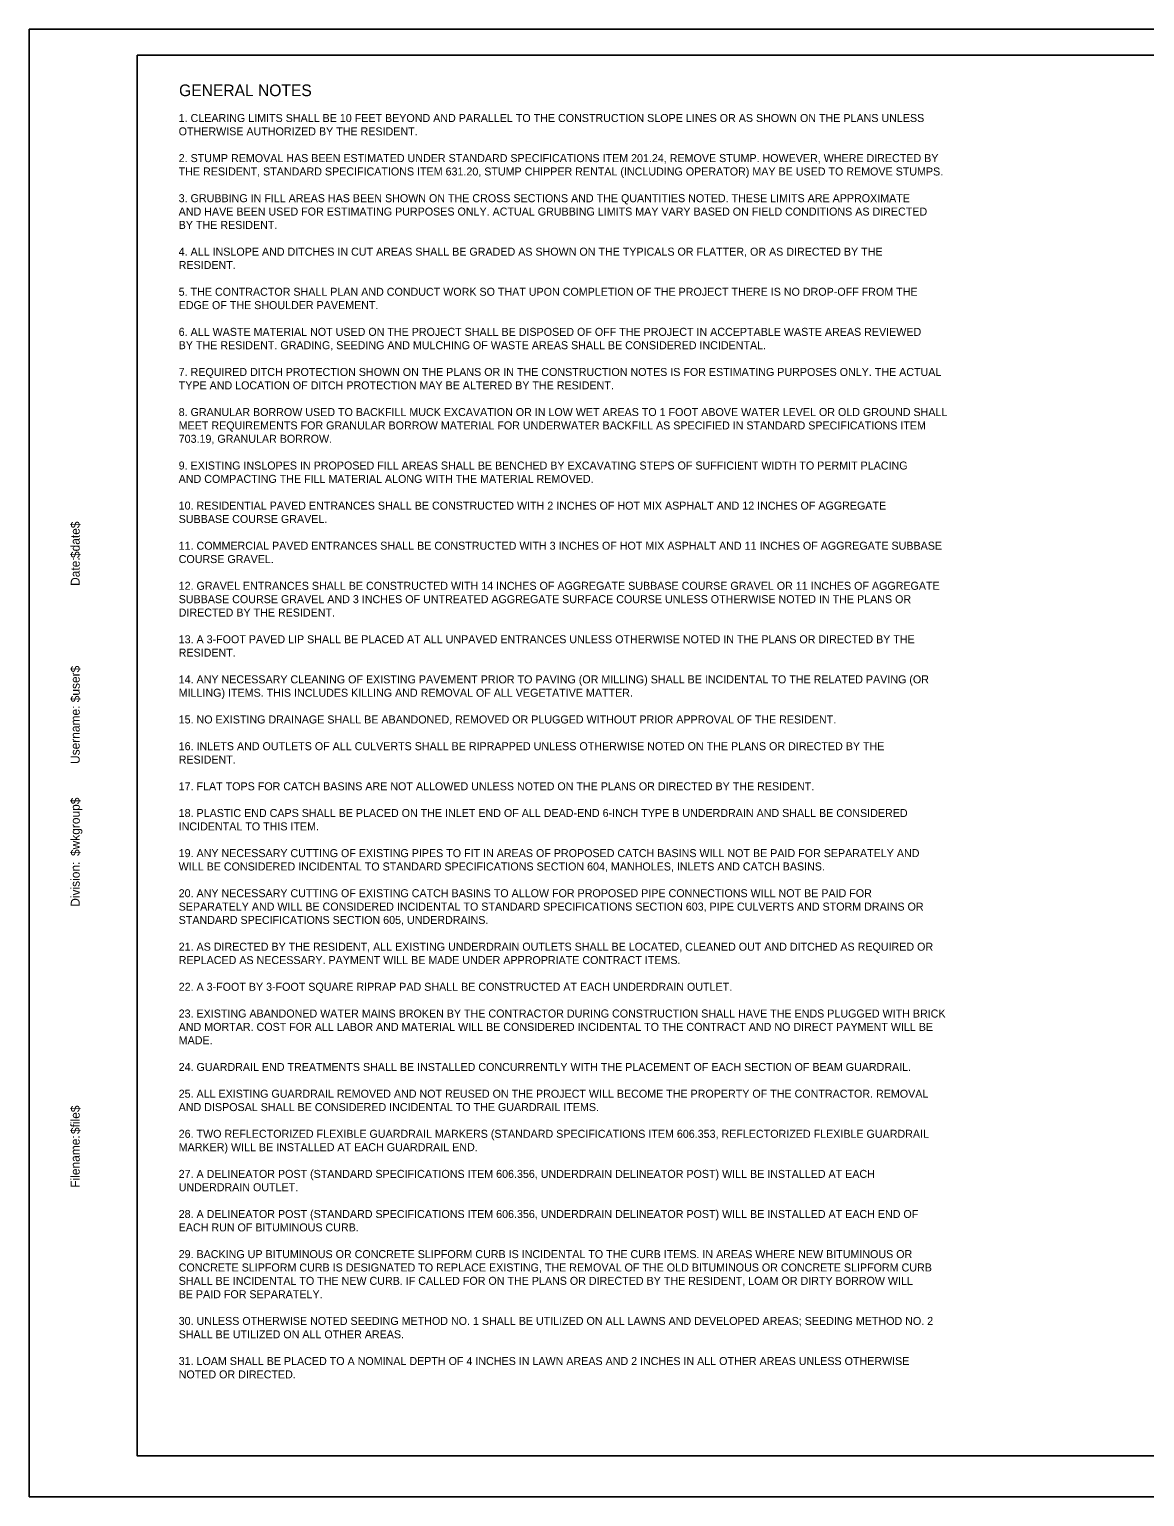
# Model space of a CAD drawing. Extents: x -0.17 to 2.66, y 2.06 to 3.89.
# Drawn here: x -0.169 to 1.225, y 2.057 to 3.89 of the extents above; entities that cross this region are included whole.
import ezdxf

# ---------------------------------------------------------------- set-up
doc = ezdxf.new("R2010")
doc.units = 0
for name, color, linetype in [('ANNOTATION', 7, 'Continuous'), ('BORDER', 7, 'Continuous'), ('PLOT BOUNDARY', 7, 'Continuous')]:
    doc.layers.add(name, color=color, linetype=linetype)

msp = doc.modelspace()

# ---------------------------------------------------------------- linework, layer by layer
at = {"layer": 'BORDER'}
msp.add_lwpolyline([(-0.0344, 3.8576), (2.6323, 3.8576), (2.6323, 2.1076), (-0.0344, 2.1076)], close=True, dxfattribs=at)
at = {"layer": 'PLOT BOUNDARY'}
msp.add_lwpolyline([(-0.1693, 2.0566), (2.6641, 2.0566), (2.6641, 3.89), (-0.1693, 3.89)], close=True, dxfattribs=at)

# ---------------------------------------------------------------- texts
at = {"layer": 'ANNOTATION'}
for s, height, p in [('GENERAL NOTES', 0.014583, (0.0179, 3.8065)), ('1. CLEARING LIMITS SHALL BE 10 FEET BEYOND AND PARALLEL TO THE CONSTRUCTION SLOPE LINES OR AS SHOWN ON THE PLANS UNLESS ', 0.01, (0.0174, 3.7742)), ('OTHERWISE AUTHORIZED BY THE RESIDENT.  ', 0.01, (0.0174, 3.7575)), ('2. STUMP REMOVAL HAS BEEN ESTIMATED UNDER STANDARD SPECIFICATIONS ITEM 201.24, REMOVE STUMP. HOWEVER, WHERE DIRECTED BY ', 0.01, (0.0174, 3.7241)), ('THE RESIDENT, STANDARD SPECIFICATIONS ITEM 631.20, STUMP CHIPPER RENTAL (INCLUDING OPERATOR) MAY BE USED TO REMOVE STUMPS.   ', 0.01, (0.0174, 3.7074)), ('AND HAVE BEEN USED FOR ESTIMATING PURPOSES ONLY. ACTUAL GRUBBING LIMITS MAY VARY BASED ON FIELD CONDITIONS AS DIRECTED ', 0.01, (0.0174, 3.6573)), ('3. GRUBBING IN FILL AREAS HAS BEEN SHOWN ON THE CROSS SECTIONS AND THE QUANTITIES NOTED. THESE LIMITS ARE APPROXIMATE ', 0.01, (0.0174, 3.674)), ('BY THE RESIDENT. ', 0.01, (0.0174, 3.6406)), ('4. ALL INSLOPE AND DITCHES IN CUT AREAS SHALL BE GRADED AS SHOWN ON THE TYPICALS OR FLATTER, OR AS DIRECTED BY THE ', 0.01, (0.0174, 3.6072)), ('RESIDENT.', 0.01, (0.0174, 3.5905)), ('5. THE CONTRACTOR SHALL PLAN AND CONDUCT WORK SO THAT UPON COMPLETION OF THE PROJECT THERE IS NO DROP-OFF FROM THE ', 0.01, (0.0174, 3.5571)), ('EDGE OF THE SHOULDER PAVEMENT. ', 0.01, (0.0174, 3.5404)), ('6. ALL WASTE MATERIAL NOT USED ON THE PROJECT SHALL BE DISPOSED OF OFF THE PROJECT IN ACCEPTABLE WASTE AREAS REVIEWED ', 0.01, (0.0174, 3.507)), ('BY THE RESIDENT. GRADING, SEEDING AND MULCHING OF WASTE AREAS SHALL BE CONSIDERED INCIDENTAL.', 0.01, (0.0174, 3.4903)), ('7. REQUIRED DITCH PROTECTION SHOWN ON THE PLANS OR IN THE CONSTRUCTION NOTES IS FOR ESTIMATING PURPOSES ONLY. THE ACTUAL ', 0.01, (0.0174, 3.4569)), ('TYPE AND LOCATION OF DITCH PROTECTION MAY BE ALTERED BY THE RESIDENT.', 0.01, (0.0174, 3.4402)), ('8. GRANULAR BORROW USED TO BACKFILL MUCK EXCAVATION OR IN LOW WET AREAS TO 1 FOOT ABOVE WATER LEVEL OR OLD GROUND SHALL ', 0.01, (0.0174, 3.4068)), ('MEET REQUIREMENTS FOR GRANULAR BORROW MATERIAL FOR UNDERWATER BACKFILL AS SPECIFIED IN STANDARD SPECIFICATIONS ITEM ', 0.01, (0.0174, 3.3901)), ('703.19, GRANULAR BORROW.', 0.01, (0.0174, 3.3734)), ('9. EXISTING INSLOPES IN PROPOSED FILL AREAS SHALL BE BENCHED BY EXCAVATING STEPS OF SUFFICIENT WIDTH TO PERMIT PLACING ', 0.01, (0.0174, 3.34)), ('AND COMPACTING THE FILL MATERIAL ALONG WITH THE MATERIAL REMOVED.', 0.01, (0.0174, 3.3233)), ('10. RESIDENTIAL PAVED ENTRANCES SHALL BE CONSTRUCTED WITH 2 INCHES OF HOT MIX ASPHALT AND 12 INCHES OF AGGREGATE ', 0.01, (0.0174, 3.2899)), ('SUBBASE COURSE GRAVEL.', 0.01, (0.0174, 3.2732)), ('11. COMMERCIAL PAVED ENTRANCES SHALL BE CONSTRUCTED WITH 3 INCHES OF HOT MIX ASPHALT AND 11 INCHES OF AGGREGATE SUBBASE ', 0.01, (0.0174, 3.2398)), ('COURSE GRAVEL.', 0.01, (0.0174, 3.2231)), ('12. GRAVEL ENTRANCES SHALL BE CONSTRUCTED WITH 14 INCHES OF AGGREGATE SUBBASE COURSE GRAVEL OR 11 INCHES OF AGGREGATE ', 0.01, (0.0174, 3.1897)), ('SUBBASE COURSE GRAVEL AND 3 INCHES OF UNTREATED AGGREGATE SURFACE COURSE UNLESS OTHERWISE NOTED IN THE PLANS OR ', 0.01, (0.0174, 3.173)), ('DIRECTED BY THE RESIDENT.', 0.01, (0.0174, 3.1563)), ('13. A 3-FOOT PAVED LIP SHALL BE PLACED AT ALL UNPAVED ENTRANCES UNLESS OTHERWISE NOTED IN THE PLANS OR DIRECTED BY THE ', 0.01, (0.0174, 3.1229)), ('RESIDENT.', 0.01, (0.0174, 3.1062)), ('14. ANY NECESSARY CLEANING OF EXISTING PAVEMENT PRIOR TO PAVING (OR MILLING) SHALL BE INCIDENTAL TO THE RELATED PAVING (OR ', 0.01, (0.0174, 3.0728)), ('MILLING) ITEMS. THIS INCLUDES KILLING AND REMOVAL OF ALL VEGETATIVE MATTER.', 0.01, (0.0174, 3.0561)), ('15. NO EXISTING DRAINAGE SHALL BE ABANDONED, REMOVED OR PLUGGED WITHOUT PRIOR APPROVAL OF THE RESIDENT.', 0.01, (0.0174, 3.0227)), ('16. INLETS AND OUTLETS OF ALL CULVERTS SHALL BE RIPRAPPED UNLESS OTHERWISE NOTED ON THE PLANS OR DIRECTED BY THE ', 0.01, (0.0174, 2.9893)), ('RESIDENT.', 0.01, (0.0174, 2.9726)), ('17. FLAT TOPS FOR CATCH BASINS ARE NOT ALLOWED UNLESS NOTED ON THE PLANS OR DIRECTED BY THE RESIDENT.', 0.01, (0.0174, 2.9392)), ('18. PLASTIC END CAPS SHALL BE PLACED ON THE INLET END OF ALL DEAD-END 6-INCH TYPE B UNDERDRAIN AND SHALL BE CONSIDERED ', 0.01, (0.0174, 2.9058)), ('INCIDENTAL TO THIS ITEM.', 0.01, (0.0174, 2.8891)), ('19. ANY NECESSARY CUTTING OF EXISTING PIPES TO FIT IN AREAS OF PROPOSED CATCH BASINS WILL NOT BE PAID FOR SEPARATELY AND ', 0.01, (0.0174, 2.8557)), ('WILL BE CONSIDERED INCIDENTAL TO STANDARD SPECIFICATIONS SECTION 604, MANHOLES, INLETS AND CATCH BASINS.', 0.01, (0.0174, 2.839)), ('20. ANY NECESSARY CUTTING OF EXISTING CATCH BASINS TO ALLOW FOR PROPOSED PIPE CONNECTIONS WILL NOT BE PAID FOR ', 0.01, (0.0174, 2.8056)), ('SEPARATELY AND WILL BE CONSIDERED INCIDENTAL TO STANDARD SPECIFICATIONS SECTION 603, PIPE CULVERTS AND STORM DRAINS OR ', 0.01, (0.0174, 2.7889)), ('STANDARD SPECIFICATIONS SECTION 605, UNDERDRAINS.', 0.01, (0.0174, 2.7722)), ('21. AS DIRECTED BY THE RESIDENT, ALL EXISTING UNDERDRAIN OUTLETS SHALL BE LOCATED, CLEANED OUT AND DITCHED AS REQUIRED OR ', 0.01, (0.0174, 2.7388)), ('REPLACED AS NECESSARY. PAYMENT WILL BE MADE UNDER APPROPRIATE CONTRACT ITEMS.', 0.01, (0.0174, 2.7221)), ('22. A 3-FOOT BY 3-FOOT SQUARE RIPRAP PAD SHALL BE CONSTRUCTED AT EACH UNDERDRAIN OUTLET.', 0.01, (0.0174, 2.6887)), ('23. EXISTING ABANDONED WATER MAINS BROKEN BY THE CONTRACTOR DURING CONSTRUCTION SHALL HAVE THE ENDS PLUGGED WITH BRICK ', 0.01, (0.0174, 2.6553)), ('AND MORTAR. COST FOR ALL LABOR AND MATERIAL WILL BE CONSIDERED INCIDENTAL TO THE CONTRACT AND NO DIRECT PAYMENT WILL BE ', 0.01, (0.0174, 2.6386)), ('MADE.', 0.01, (0.0174, 2.6219)), ('24. GUARDRAIL END TREATMENTS SHALL BE INSTALLED CONCURRENTLY WITH THE PLACEMENT OF EACH SECTION OF BEAM GUARDRAIL.', 0.01, (0.0174, 2.5885)), ('AND DISPOSAL SHALL BE CONSIDERED INCIDENTAL TO THE GUARDRAIL ITEMS.', 0.01, (0.0174, 2.5384)), ('25. ALL EXISTING GUARDRAIL REMOVED AND NOT REUSED ON THE PROJECT WILL BECOME THE PROPERTY OF THE CONTRACTOR. REMOVAL ', 0.01, (0.0174, 2.5551)), ('26. TWO REFLECTORIZED FLEXIBLE GUARDRAIL MARKERS (STANDARD SPECIFICATIONS ITEM 606.353, REFLECTORIZED FLEXIBLE GUARDRAIL ', 0.01, (0.0174, 2.505)), ('MARKER) WILL BE INSTALLED AT EACH GUARDRAIL END.  ', 0.01, (0.0174, 2.4883)), ('27. A DELINEATOR POST (STANDARD SPECIFICATIONS ITEM 606.356, UNDERDRAIN DELINEATOR POST) WILL BE INSTALLED AT EACH ', 0.01, (0.0174, 2.4549)), ('UNDERDRAIN OUTLET.', 0.01, (0.0174, 2.4382)), ('28. A DELINEATOR POST (STANDARD SPECIFICATIONS ITEM 606.356, UNDERDRAIN DELINEATOR POST) WILL BE INSTALLED AT EACH END OF ', 0.01, (0.0174, 2.4048)), ('EACH RUN OF BITUMINOUS CURB.   ', 0.01, (0.0174, 2.3881)), ('29. BACKING UP BITUMINOUS OR CONCRETE SLIPFORM CURB IS INCIDENTAL TO THE CURB ITEMS. IN AREAS WHERE NEW BITUMINOUS OR ', 0.01, (0.0174, 2.3547)), ('CONCRETE SLIPFORM CURB IS DESIGNATED TO REPLACE EXISTING, THE REMOVAL OF THE OLD BITUMINOUS OR CONCRETE SLIPFORM CURB ', 0.01, (0.0174, 2.338)), ('SHALL BE INCIDENTAL TO THE NEW CURB. IF CALLED FOR ON THE PLANS OR DIRECTED BY THE RESIDENT, LOAM OR DIRTY BORROW WILL ', 0.01, (0.0174, 2.3213)), ('BE PAID FOR SEPARATELY.', 0.01, (0.0174, 2.3046)), ('30. UNLESS OTHERWISE NOTED SEEDING METHOD NO. 1 SHALL BE UTILIZED ON ALL LAWNS AND DEVELOPED AREAS; SEEDING METHOD NO. 2 ', 0.01, (0.0174, 2.2712)), ('SHALL BE UTILIZED ON ALL OTHER AREAS.', 0.01, (0.0174, 2.2545)), ('31. LOAM SHALL BE PLACED TO A NOMINAL DEPTH OF 4 INCHES IN LAWN AREAS AND 2 INCHES IN ALL OTHER AREAS UNLESS OTHERWISE ', 0.01, (0.0174, 2.2211)), ('NOTED OR DIRECTED.', 0.01, (0.0174, 2.2044))]:
    msp.add_text(s, height=height, dxfattribs=at).set_placement(p)
at = {"layer": 'BORDER'}
for s, p in [('$date$', (-0.1063, 3.2294)), ('Date:', (-0.1063, 3.1946)), ('$user$', (-0.1063, 3.0492)), ('Username:', (-0.1063, 2.9721)), ('$wkgroup$', (-0.1063, 2.8571)), ('Division:', (-0.1063, 2.7937)), ('$file$', (-0.1063, 2.5097)), ('Filename:', (-0.1063, 2.4426))]:
    msp.add_text(s, height=0.01116, rotation=90, dxfattribs=at).set_placement(p)

doc.saveas('drawing.dxf')
